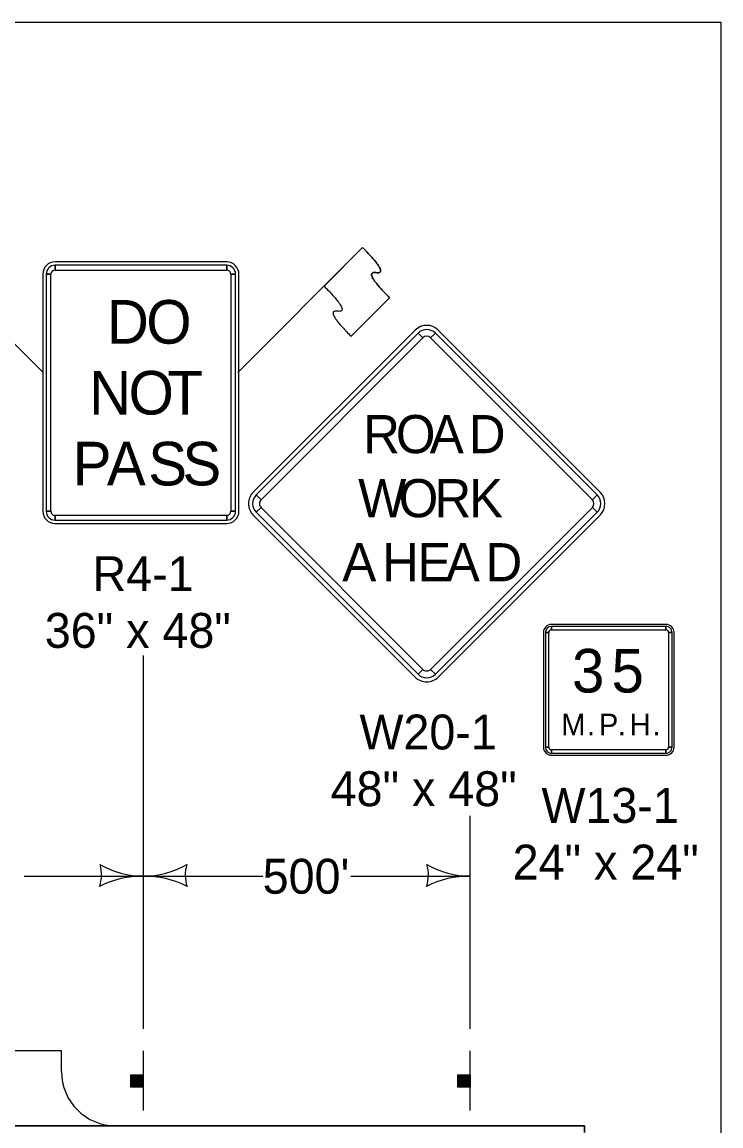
# Model space of a CAD drawing. Extents: x -2134934 to -2122394, y -2140205 to -2137036.
# Drawn here: x -2132120 to -2131799, y -2137542 to -2137036 of the extents above; entities that cross this region are included whole.
import ezdxf

# ---------------------------------------------------------------- set-up
doc = ezdxf.new("R2010")
doc.units = 0
for name, color, linetype in [('Barrier', 7, 'Continuous'), ('BridgeSuperStructureExisting', 7, 'Continuous'), ('Default', 7, 'Continuous'), ('DsnShtPlotIdentification', 7, 'Continuous'), ('TC_Barrier', 7, 'Continuous')]:
    doc.layers.add(name, color=color, linetype=linetype)

msp = doc.modelspace()

# ---------------------------------------------------------------- linework, layer by layer
at = {"layer": 'Barrier'}
for p, q in [((-2132110.46, -2137196.68), (-2132167.8, -2137139.38)), ((-2132021.17, -2137196.68), (-2131963.85, -2137139.36)), ((-2131963.85, -2137139.36), (-2131981.54, -2137157.04)), ((-2132026.22, -2137145.92), (-2132104.97, -2137145.92)), ((-2132104.97, -2137149.67), (-2132104.97, -2137147.48)), ((-2132026.22, -2137147.48), (-2132026.22, -2137149.67)), ((-2132110.6, -2137151.54), (-2132110.6, -2137260.29)), ((-2132109.04, -2137151.54), (-2132106.85, -2137151.54)), ((-2132024.35, -2137151.54), (-2132022.16, -2137151.54)), ((-2132020.6, -2137260.29), (-2132020.6, -2137151.54)), ((-2131969.15, -2137180.03), (-2131951.48, -2137162.35)), ((-2131939.75, -2137177.23), (-2132014, -2137251.47)), ((-2131854.9, -2137251.47), (-2131929.14, -2137177.23)), ((-2131938.42, -2137178.55), (-2131936.21, -2137180.76)), ((-2131932.68, -2137180.76), (-2131930.47, -2137178.55)), ((-2132010.46, -2137255.01), (-2132012.67, -2137252.8)), ((-2131856.22, -2137252.8), (-2131858.43, -2137255.01)), ((-2132012.67, -2137260.75), (-2132010.46, -2137258.54)), ((-2131858.43, -2137258.54), (-2131856.22, -2137260.75)), ((-2132106.85, -2137260.29), (-2132109.04, -2137260.29)), ((-2132104.97, -2137264.35), (-2132104.97, -2137262.17)), ((-2132026.22, -2137262.17), (-2132026.22, -2137264.35)), ((-2132022.16, -2137260.29), (-2132024.35, -2137260.29)), ((-2132014, -2137262.08), (-2131939.75, -2137336.33)), ((-2131929.14, -2137336.33), (-2131854.9, -2137262.08)), ((-2132104.97, -2137265.92), (-2132026.22, -2137265.92)), ((-2131824.68, -2137312.17), (-2131877.18, -2137312.17)), ((-2131877.18, -2137314.67), (-2131877.18, -2137313.1)), ((-2131824.68, -2137313.1), (-2131824.68, -2137314.67)), ((-2131880.93, -2137315.92), (-2131880.93, -2137368.42)), ((-2131879.99, -2137315.92), (-2131878.43, -2137315.92)), ((-2131823.43, -2137315.92), (-2131821.86, -2137315.92)), ((-2131820.93, -2137368.42), (-2131820.93, -2137315.92)), ((-2131936.21, -2137332.79), (-2131938.42, -2137335)), ((-2131930.47, -2137335), (-2131932.68, -2137332.79)), ((-2131878.43, -2137368.42), (-2131879.99, -2137368.42)), ((-2131877.18, -2137371.23), (-2131877.18, -2137369.67)), ((-2131824.68, -2137369.67), (-2131824.68, -2137371.23)), ((-2131821.86, -2137368.42), (-2131823.43, -2137368.42)), ((-2131877.18, -2137372.17), (-2131824.68, -2137372.17))]:
    msp.add_line(p, q, dxfattribs=at)
for points in [[(-2132026.22, -2137147.48), (-2132104.97, -2137147.48), (-2132104.97, -2137149.67), (-2132026.22, -2137149.67), (-2132026.22, -2137147.48)], [(-2132109.04, -2137151.54), (-2132109.04, -2137260.29), (-2132106.85, -2137260.29), (-2132106.85, -2137151.54), (-2132109.04, -2137151.54)], [(-2132022.16, -2137260.29), (-2132022.16, -2137151.54), (-2132024.35, -2137151.54), (-2132024.35, -2137260.29), (-2132022.16, -2137260.29)], [(-2131938.42, -2137178.55), (-2132012.67, -2137252.8), (-2132010.46, -2137255.01), (-2131936.21, -2137180.76), (-2131938.42, -2137178.55)], [(-2131856.22, -2137252.8), (-2131930.47, -2137178.55), (-2131932.68, -2137180.76), (-2131858.43, -2137255.01), (-2131856.22, -2137252.8)], [(-2132012.67, -2137260.75), (-2131938.42, -2137335), (-2131936.21, -2137332.79), (-2132010.46, -2137258.54), (-2132012.67, -2137260.75)], [(-2131930.47, -2137335), (-2131856.22, -2137260.75), (-2131858.43, -2137258.54), (-2131932.68, -2137332.79), (-2131930.47, -2137335)], [(-2132104.97, -2137264.35), (-2132026.22, -2137264.35), (-2132026.22, -2137262.17), (-2132104.97, -2137262.17), (-2132104.97, -2137264.35)], [(-2131824.68, -2137313.1), (-2131877.18, -2137313.1), (-2131877.18, -2137314.67), (-2131824.68, -2137314.67), (-2131824.68, -2137313.1)], [(-2131879.99, -2137315.92), (-2131879.99, -2137368.42), (-2131878.43, -2137368.42), (-2131878.43, -2137315.92), (-2131879.99, -2137315.92)], [(-2131821.86, -2137368.42), (-2131821.86, -2137315.92), (-2131823.43, -2137315.92), (-2131823.43, -2137368.42), (-2131821.86, -2137368.42)], [(-2131877.18, -2137371.23), (-2131824.68, -2137371.23), (-2131824.68, -2137369.67), (-2131877.18, -2137369.67), (-2131877.18, -2137371.23)]]:
    msp.add_lwpolyline(points, close=True, dxfattribs=at)
for centre, radius, start, end in [((-2132104.97, -2137151.54), 5.62, 90.0002, 179.9998), ((-2132104.97, -2137151.54), 4.06, 90.0002, 179.9998), ((-2132026.22, -2137151.54), 5.62, 0, 90.0002), ((-2132026.22, -2137151.54), 4.06, 0, 90.0002), ((-2132104.97, -2137151.54), 1.87, 90.0002, 179.9998), ((-2132026.22, -2137151.54), 1.87, 0, 90.0002), ((-2131934.45, -2137182.53), 7.5, 45, 134.9997), ((-2131934.45, -2137182.53), 5.62, 45, 134.9997), ((-2131934.45, -2137182.53), 2.5, 45, 134.9997), ((-2132008.69, -2137256.78), 7.5, 134.9997, 225), ((-2132008.69, -2137256.78), 5.62, 134.9997, 225), ((-2131860.2, -2137256.78), 5.62, 315.0002, 44.9998), ((-2131860.2, -2137256.78), 7.5, 315.0002, 44.9998), ((-2132008.69, -2137256.78), 2.5, 134.9997, 225), ((-2131860.2, -2137256.78), 2.5, 315.0002, 44.9998), ((-2132104.97, -2137260.29), 5.62, 179.9998, 270.0001), ((-2132104.97, -2137260.29), 4.06, 179.9998, 270.0001), ((-2132104.97, -2137260.29), 1.87, 179.9998, 270.0001), ((-2132026.22, -2137260.29), 5.62, 270.0001, 0.0003), ((-2132026.22, -2137260.29), 4.06, 270.0001, 0.0003), ((-2132026.22, -2137260.29), 1.87, 270.0001, 0.0003), ((-2131877.18, -2137315.92), 3.75, 90.0002, 179.9998), ((-2131877.18, -2137315.92), 2.81, 90.0002, 179.9998), ((-2131877.18, -2137315.92), 1.25, 90.0002, 179.9998), ((-2131824.68, -2137315.92), 3.75, 0, 90.0002), ((-2131824.68, -2137315.92), 2.81, 0, 90.0002), ((-2131824.68, -2137315.92), 1.25, 0, 90.0002), ((-2131934.45, -2137331.02), 5.62, 225, 315.0002), ((-2131934.45, -2137331.02), 2.5, 225, 315.0002), ((-2131934.45, -2137331.02), 7.5, 225, 315.0002), ((-2131877.18, -2137368.42), 3.75, 179.9998, 270.0001), ((-2131877.18, -2137368.42), 2.81, 179.9998, 270.0001), ((-2131877.18, -2137368.42), 1.25, 179.9998, 270.0001), ((-2131824.68, -2137368.42), 3.75, 270.0001, 0.0003), ((-2131824.68, -2137368.42), 2.81, 270.0001, 0.0003), ((-2131824.68, -2137368.42), 1.25, 270.0001, 0.0003)]:
    msp.add_arc(centre, radius, start, end, dxfattribs=at)
for points in [[(-2131951.48, -2137162.35), (-2131963.85, -2137149.98), (-2131951.48, -2137151.75), (-2131963.85, -2137139.36)], [(-2131981.54, -2137157.04), (-2131969.16, -2137169.43), (-2131981.53, -2137167.66), (-2131969.15, -2137180.03)]]:
    msp.add_open_spline(points, degree=2, dxfattribs=at)
at = {"layer": 'BridgeSuperStructureExisting'}
for p, q in [((-2132064.45, -2137497.66), (-2132064.45, -2137326.42)), ((-2131914.45, -2137497.66), (-2131914.45, -2137399.97)), ((-2132119.2, -2137427.66), (-2132064.45, -2137427.66)), ((-2132064.45, -2137427.66), (-2132009.7, -2137427.66)), ((-2131969.2, -2137427.66), (-2131914.45, -2137427.66)), ((-2132064.45, -2137535.16), (-2132064.45, -2137507.66)), ((-2131914.45, -2137535.16), (-2131914.45, -2137507.66)), ((-2132069.77, -2137524.3), (-2132069.77, -2137518.71)), ((-2132069.45, -2137518.71), (-2132069.45, -2137524.3)), ((-2132069.23, -2137524.3), (-2132069.23, -2137518.71)), ((-2132068.91, -2137518.71), (-2132068.91, -2137524.3)), ((-2132068.69, -2137524.3), (-2132068.7, -2137518.71)), ((-2132068.27, -2137518.71), (-2132068.25, -2137524.3)), ((-2132068.05, -2137524.3), (-2132068.05, -2137518.71)), ((-2132067.62, -2137518.71), (-2132067.62, -2137524.3)), ((-2132067.24, -2137524.3), (-2132067.24, -2137518.71)), ((-2132066.92, -2137518.71), (-2132066.9, -2137524.3)), ((-2132066.7, -2137524.3), (-2132066.7, -2137518.71)), ((-2132066.43, -2137518.71), (-2132066.43, -2137524.3)), ((-2132066.1, -2137524.3), (-2132066.1, -2137518.71)), ((-2132065.89, -2137518.71), (-2132065.89, -2137524.3)), ((-2132065.67, -2137524.3), (-2132065.67, -2137518.71)), ((-2132065.4, -2137518.71), (-2132065.4, -2137524.3)), ((-2132065.14, -2137524.3), (-2132065.14, -2137518.71)), ((-2132064.86, -2137518.71), (-2132064.86, -2137524.3)), ((-2131919.77, -2137524.3), (-2131919.77, -2137518.71)), ((-2131919.45, -2137518.71), (-2131919.45, -2137524.3)), ((-2131919.23, -2137524.3), (-2131919.23, -2137518.71)), ((-2131918.91, -2137518.71), (-2131918.91, -2137524.3)), ((-2131918.69, -2137524.3), (-2131918.7, -2137518.71)), ((-2131918.27, -2137518.71), (-2131918.25, -2137524.3)), ((-2131918.05, -2137524.3), (-2131918.05, -2137518.71)), ((-2131917.62, -2137518.71), (-2131917.62, -2137524.3)), ((-2131917.24, -2137524.3), (-2131917.24, -2137518.71)), ((-2131916.92, -2137518.71), (-2131916.9, -2137524.3)), ((-2131916.7, -2137524.3), (-2131916.7, -2137518.71)), ((-2131916.43, -2137518.71), (-2131916.43, -2137524.3)), ((-2131916.1, -2137524.3), (-2131916.1, -2137518.71)), ((-2131915.89, -2137518.71), (-2131915.89, -2137524.3)), ((-2131915.67, -2137524.3), (-2131915.67, -2137518.71)), ((-2131915.4, -2137518.71), (-2131915.4, -2137524.3)), ((-2131915.14, -2137524.3), (-2131915.14, -2137518.71)), ((-2131914.86, -2137518.71), (-2131914.86, -2137524.3)), ((-2132187.05, -2137542.16), (-2132077.05, -2137542.16))]:
    msp.add_line(p, q, dxfattribs=at)
msp.add_lwpolyline([(-2132102.05, -2137517.16), (-2132102.05, -2137507.67), (-2132162.05, -2137507.67), (-2132162.05, -2137517.16)], dxfattribs=at)
for points in [[(-2132064.54, -2137518.71), (-2132064.54, -2137524.34), (-2132070.17, -2137524.34), (-2132070.17, -2137518.71)], [(-2131914.54, -2137518.71), (-2131914.54, -2137524.34), (-2131920.17, -2137524.34), (-2131920.17, -2137518.71)]]:
    msp.add_lwpolyline(points, close=True, dxfattribs=at)
for centre, radius, start, end in [((-2132100.06, -2137427.04), 16.42, 341.2666, 16.7334), ((-2132063.69, -2137385.17), 42.5, 240.9275, 268.9824), ((-2132065.2, -2137385.17), 42.5, 271.0176, 299.0725), ((-2132028.83, -2137427.04), 16.42, 163.2666, 198.7334), ((-2131950.06, -2137427.04), 16.42, 341.2666, 16.7334), ((-2131913.69, -2137385.17), 42.5, 240.9275, 268.9824), ((-2132065.18, -2137470.15), 42.5, 89.0176, 117.0725), ((-2132063.72, -2137470.15), 42.5, 62.9275, 90.9824), ((-2131915.18, -2137470.15), 42.5, 89.0176, 117.0725), ((-2132077.05, -2137517.16), 25, 180, 270)]:
    msp.add_arc(centre, radius, start, end, dxfattribs=at)
at = {"layer": 'Default'}
msp.add_lwpolyline([(-2134934.44, -2137035.95), (-2131799.45, -2137035.95), (-2131799.45, -2139045.94), (-2134934.44, -2139045.94)], close=True, dxfattribs=at)
at = {"layer": 'DsnShtPlotIdentification'}
for p, q in [((-2131861.99, -2137542.16), (-2132547.01, -2137542.16)), ((-2131861.99, -2137542.16), (-2131861.99, -2137545.16)), ((-2131861.99, -2137545.16), (-2131861.99, -2137542.16))]:
    msp.add_line(p, q, dxfattribs=at)
msp.add_lwpolyline([(-2133174.44, -2137542.16), (-2131861.99, -2137542.16)], dxfattribs=at)
at = {"layer": 'TC_Barrier'}
msp.add_line((-2131951.48, -2137162.35), (-2131969.15, -2137180.03), dxfattribs=at)
for points in [[(-2131963.85, -2137139.36), (-2131951.48, -2137151.75), (-2131963.85, -2137149.98), (-2131951.48, -2137162.35)], [(-2131981.54, -2137157.04), (-2131969.16, -2137169.43), (-2131981.53, -2137167.66), (-2131969.15, -2137180.03)]]:
    msp.add_open_spline(points, degree=2, dxfattribs=at)

# ---------------------------------------------------------------- texts
at = {"layer": 'Barrier'}
for s, height, p in [('O', 20, (-2132063.1, -2137183.42)), ('D', 20, (-2132081.22, -2137183.42)), ('N', 20, (-2132089.35, -2137215.92)), ('O', 20, (-2132071.22, -2137215.92)), ('T', 20, (-2132053.41, -2137215.92)), ('R', 17.5, (-2131963.61, -2137233.65)), ('O', 17.5, (-2131948.6, -2137233.65)), ('A', 17.5, (-2131933.05, -2137233.65)), ('D', 17.5, (-2131915.17, -2137233.65)), ('P', 20, (-2132096.86, -2137248.42)), ('A', 20, (-2132081.18, -2137248.42)), ('S', 20, (-2132062.21, -2137248.42)), ('S', 20, (-2132046.52, -2137248.42)), ('W', 17.5, (-2131965.89, -2137263.03)), ('O', 17.5, (-2131947.3, -2137263.03)), ('R', 17.5, (-2131930.89, -2137263.03)), ('K', 17.5, (-2131915.03, -2137263.03)), ('A', 17.5, (-2131973.17, -2137292.4)), ('H', 17.5, (-2131954.96, -2137292.4)), ('E', 17.5, (-2131938.73, -2137292.4)), ('A', 17.5, (-2131925.69, -2137292.4)), ('D', 17.5, (-2131907.48, -2137292.4)), ('R4-1', 16, (-2132087.76, -2137296.92)), ('36" x 48"', 16, (-2132109.67, -2137322.92)), ('3', 20, (-2131867.78, -2137343.41)), ('5', 20, (-2131849.65, -2137343.41)), ('W20-1', 16, (-2131965.3, -2137369.52)), ('M', 10, (-2131872.7, -2137363.1)), ('P', 10, (-2131855.45, -2137363.1)), ('H', 10, (-2131841.33, -2137363.1)), ('.', 10, (-2131860.91, -2137363.1)), ('.', 10, (-2131846.79, -2137363.1)), ('.', 10, (-2131830.86, -2137363.1)), ('48" x 48"', 16, (-2131978.51, -2137395.52)), ('W13-1', 16, (-2131881.78, -2137403.17)), ('24" x 24"', 16, (-2131894.99, -2137429.17))]:
    msp.add_text(s, height=height, dxfattribs=at).set_placement(p)
at = {"layer": 'BridgeSuperStructureExisting'}
msp.add_text("500'", height=16, dxfattribs=at).set_placement((-2132009.7, -2137435.66))

doc.saveas('drawing.dxf')
